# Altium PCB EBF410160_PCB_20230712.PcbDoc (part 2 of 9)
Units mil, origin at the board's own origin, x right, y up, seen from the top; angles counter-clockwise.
Board outline 5393.69 x 3858.26 mil, 6 copper layers (TOP, GND02, ART03, POW04, GND05, BOTTOM), stack 47.2 mil thick; 572 components, 434 nets, 2057 pads, 1177 vias.
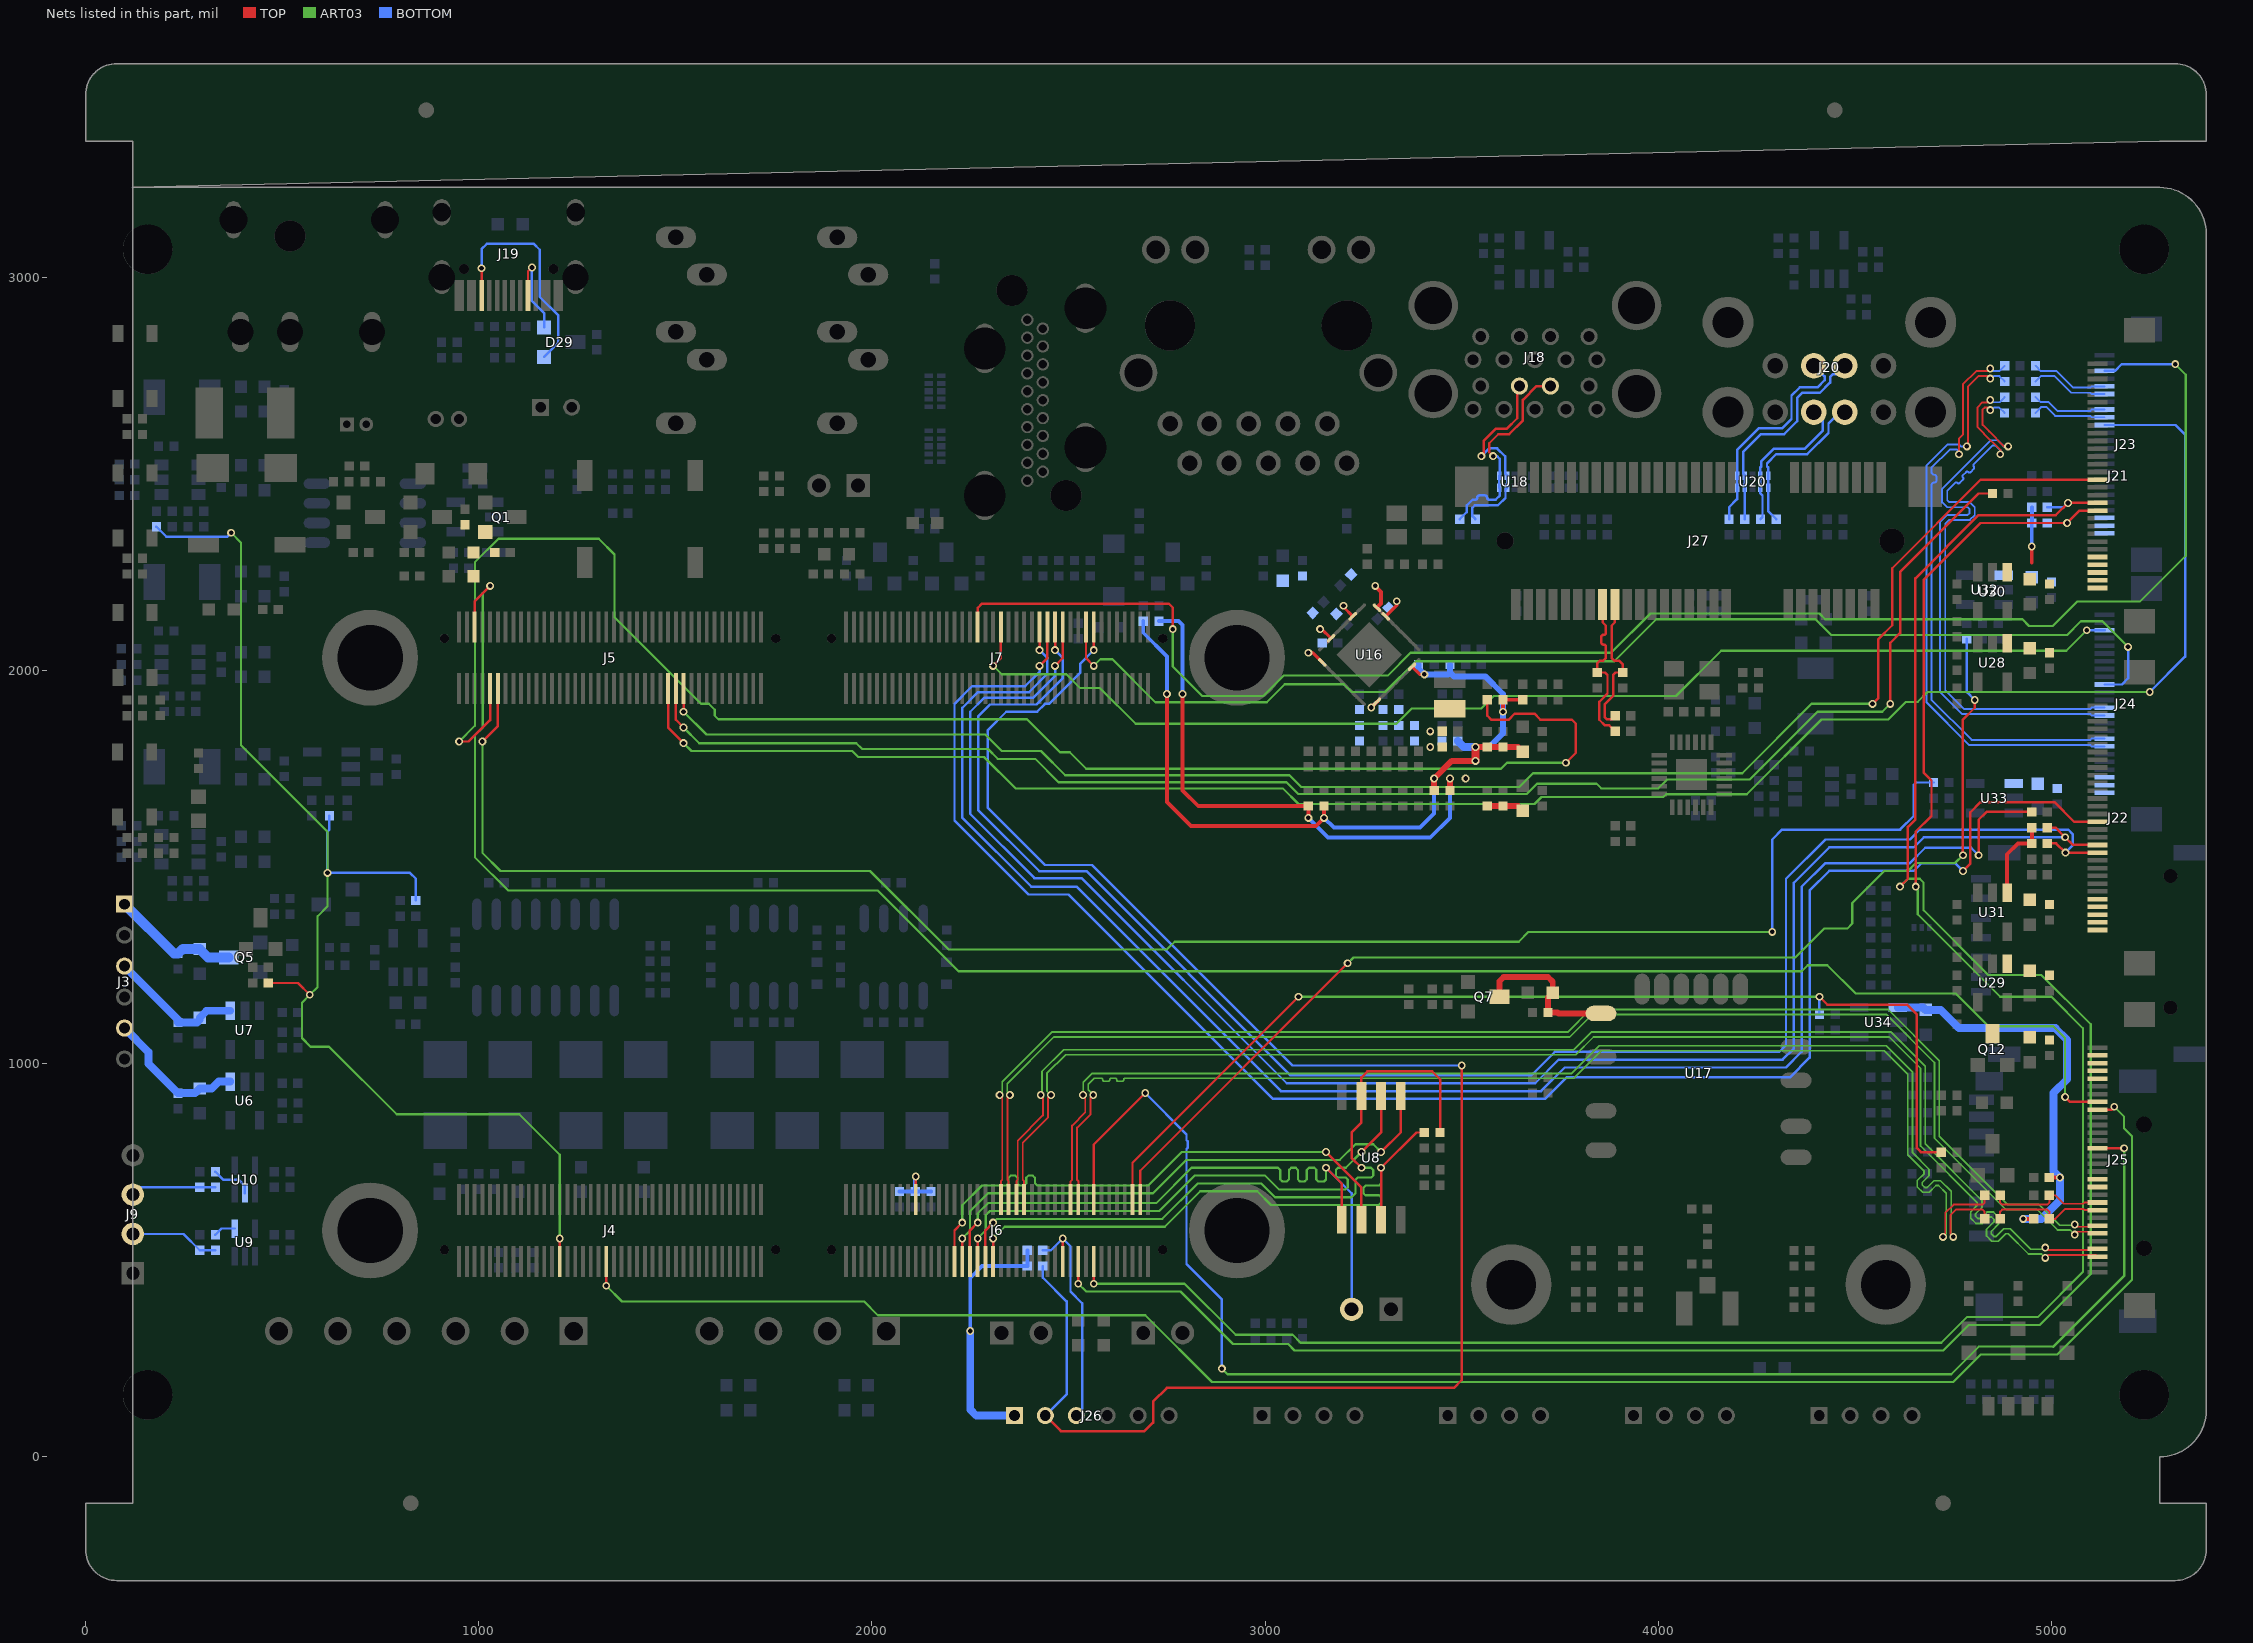
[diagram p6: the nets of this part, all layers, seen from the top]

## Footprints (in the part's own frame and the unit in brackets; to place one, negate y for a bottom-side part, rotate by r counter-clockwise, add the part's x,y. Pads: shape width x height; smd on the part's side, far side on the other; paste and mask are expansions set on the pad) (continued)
HDMI-SMD [mm] "HDMI-SMD"
  round 0.8 / inner round 1.524 / far side round 0.8 hole 0.55: 1(1.194,0.5) 3(0.039,0.5) 4(-0.531,-0.5) 6(-1.687,-0.5) 7(-2.271,0.5) 9(-3.425,0.5) 10(-3.998,-0.5) 12(-5.154,-0.5) 13(-5.736,0.5) 14(-6.31,-0.5) 15(-6.891,0.5) 16(-7.467,-0.5) 18(-8.623,-0.5) 19(-9.2,0.5)
  round 0.8 hole 0.55: 2(0.626,-0.5) 5(-1.116,0.5) 8(-2.843,-0.5) 11(-4.581,0.5) 17(-8.045,0.5)
  oval 3.2x1.4 / inner round 1.524 / far side oval 3.2x1.4 hole 2.7 slot 0.9 at 90 deg: G1(-10.156,3.25) G2(-0.656,3.25) G3(-7.056,-3.25) G4(1.945,-3.25)
  round 2 hole 2 unplated: ""(-10.156,-2) ""(3.094,1.5)
  silkscreen extent -11.51,-3.83 11.73,3.79, body extent -11.86,-4.05 11.86,4.05, height 3.81
HY911130A [mm] "HY911130A"
  round 1.6 / inner round 1.524 / far side round 1.6 hole 1: 1(5.72,-8.74) 2(4.45,-6.2) 3(3.18,-8.74) 4(1.91,-6.2) 5(0.64,-8.74) 6(-0.63,-6.2) 7(-1.9,-8.74) 8(-3.17,-6.2) 9(-4.44,-8.74) 10(-5.71,-6.2)
  round 1.8 / inner round 1.524 / far side round 1.8 hole 1.2: 11(6.625,5.05) 12(4.085,5.05) 13(-4.085,5.05) 14(-6.625,5.05)
  round 2.43 hole 1.83: 15(7.745,-2.9) 16(-7.745,-2.9)
  round 3.25 hole 3.25 unplated: ""(-5.715,0.15) ""(5.715,0.15)
  silkscreen extent -8.02,-10.25 8.02,11.05, body extent -9.2,-11.05 9.2,11.05, height 3.81
L0603 [mil] "L0603"
  rect 31.5x31.5 smd: 1(-31.5,0) 2(31.5,0)
  silkscreen extent -54,-24 55,24, body extent -47,-16 47,16, height 150
L2520 [mil] "L2520"
  rect 44x80 smd: 1(-37.75,0) 2(37.75,0)
  silkscreen extent -68,-48 68,48, body extent -65,-45 65,45, height 150
L4520 [mil] "L4520"
  rect 55.12x90.55 smd: 1(-70.97,-0.1) 2(70.77,-0.1)
  silkscreen extent -91,-87 90,87, body extent -91,-87 91,87, height 150
LED0603 [mil] "LED0603"
  rect 36.61x38.58 smd: 1(30.32,0) 2(-30.31,0)
  silkscreen extent -60,-31 80,31, body extent -49,-19 49,19, height 150
MARK#1 [mil] "MARK"
  round 40 smd far side: 1(-39.37,3543.3) 1(0,0) 1(3582.67,0) 1(3858.26,3543.3)
  body extent -79,-40 3898,3583, height 150
MARK#2 [mil] "MARK"
  round 40 smd far side: 1(-3622.04,3543.3) 1(-3582.67,0) 1(0,0) 1(275.59,3543.3)
  body extent -3662,-40 316,3583, height 150
MARK#3 [mil] "MARK"
  round 40 smd far side: 1(-3897.63,0) 1(-3858.26,-3543.3) 1(-275.59,-3543.3) 1(0,0)
  body extent -3938,-3583 40,40, height 150
MARK#4 [mil] "MARK"
  round 40 smd far side: 1(0,0) 1(39.37,-3543.3) 1(3622.04,-3543.3) 1(3897.63,0)
  body extent -40,-3583 3938,40, height 150
MARK#5 [mil] "MARK"
  round 40 smd: 1(-39.37,-3543.3) 1(0,0) 1(3582.67,0) 1(3858.26,-3543.3)
  body extent -79,-3583 3898,40, height 150
MARK#6 [mil] "MARK"
  round 40 smd: 1(-3622.04,-3543.3) 1(-3582.67,0) 1(0,0) 1(275.59,-3543.3)
  body extent -3662,-3583 316,40, height 150
MARK#7 [mil] "MARK"
  round 40 smd: 1(-3897.63,0) 1(-3858.26,3543.3) 1(-275.59,3543.3) 1(0,0)
  body extent -3938,-40 40,3583, height 150
MARK#8 [mil] "MARK"
  round 40 smd: 1(0,0) 1(39.37,3543.3) 1(3622.04,3543.3) 1(3897.63,0)
  body extent -40,-40 3938,3583, height 150
NANO_SIM [mm] "NANO_SIM"
  rect 0.5x1.3 smd: 1(0.25,6.94) 2(-2.29,6.94) 3(-4.83,6.94) 4(2.47,6.94) 5(1.52,6.94) 6(-1.02,6.94) 7(-3.56,6.94)
  rect 1x2.1 smd: 8(-6.5,5.46) 9(6.5,5.46) 10(-6.5,-6.54) 11(6.5,-6.54)
  round 0.9 hole 0.9 unplated: ""(-5,-5.29) ""(3.5,-5.29)
  silkscreen extent -6.14,-7.6 6.14,5.9, body extent -7.05,-7.64 7.05,7.64, height 3.81
NPTH_M3 [mm] "NPTH_M3"
  round 3.2 / inner round 1.524 / far side round 3.2 hole 3.2 unplated: 1(0,0)
  body extent -3.11,-3.11 3.11,3.11, height 3.81
PCIE_52P [mm] "PCIE_52P"
  rect 0.6x2 smd: 1(-11.8,-4.1) 2(-11.4,4.1) 3(-11,-4.1) 4(-10.6,4.1) 5(-10.2,-4.1) 6(-9.8,4.1) 7(-9.4,-4.1) 8(-9,4.1) 9(-8.6,-4.1) 10(-8.2,4.1) 11(-7.8,-4.1) 12(-7.4,4.1) 13(-7,-4.1) 14(-6.6,4.1) 15(-6.2,-4.1) 16(-5.8,4.1) 17(-2.2,-4.1) 18(-1.8,4.1) 19(-1.4,-4.1) 20(-1,4.1) 21(-0.6,-4.1) 22(-0.2,4.1) 23(0.2,-4.1) 24(0.6,4.1) 25(1,-4.1) 26(1.4,4.1) 27(1.8,-4.1) 28(2.2,4.1) 29(2.6,-4.1) 30(3,4.1) 31(3.4,-4.1) 32(3.8,4.1) 33(4.2,-4.1) 34(4.6,4.1) 35(5,-4.1) 36(5.4,4.1) 37(5.8,-4.1) 38(6.2,4.1) 39(6.6,-4.1) 40(7,4.1) 41(7.4,-4.1) 42(7.8,4.1) 43(8.2,-4.1) 44(8.6,4.1) 45(9,-4.1) 46(9.4,4.1) 47(9.8,-4.1) 48(10.2,4.1) 49(10.6,-4.1) 50(11,4.1) 51(11.4,-4.1) 52(11.8,4.1)
  rect 2.15x2.6 smd: 53(14.65,-3.5) 54(-14.65,-3.5)
  round 1.6 hole 1.6 unplated: ""(-12.5,0)
  round 1.1 hole 1.1 unplated: ""(12.5,0)
  silkscreen extent -15,-4.6 15,49.64, body extent -15.8,-5.2 15.8,5.2, height 3.81
PH-1X2-2P0_L [mm] "PH-1X2-2P0_L"
  rect 1.1x1.1 / inner round 1.524 / far side rect 1.1x1.1 hole 0.7: 1(-1,-0.6)
  round 1.1 / inner round 1.524 / far side round 1.1 hole 0.7: 2(1,-0.6)
  silkscreen extent -3,-2.6 3,2.6, body extent -3.1,-2.7 3.1,2.7, height 3.81
PH-1X4-2P0 [mm] "PH-1X4-2P0"
  rect 1.1x1.1 / inner round 1.524 / far side rect 1.1x1.1 hole 0.7: 1(-3,-0.6)
  round 1.1 / inner round 1.524 / far side round 1.1 hole 0.7: 2(-1,-0.6) 3(1,-0.6)
  round 1.1 hole 0.7: 4(3,-0.6)
  silkscreen extent -5,-2.6 5,2.6, body extent -5.1,-2.7 5.1,2.7, height 3.81
PH-1X6-2P0#1 [mm] "PH-1X6-2P0"
  rect 1.1x1.1 / inner round 1.524 / far side rect 1.1x1.1 hole 0.7: 1(-5,-0.6)
  round 1.1 hole 0.7: 2(-3,-0.6) 4(1,-0.6) 6(5,-0.6)
  round 1.1 / inner round 1.524 / far side round 1.1 hole 0.7: 3(-1,-0.6) 5(3,-0.6)
  silkscreen extent -7,-2.6 7,2.6, body extent -7.1,-2.7 7.1,2.7, height 3.81
PH-1X6-2P0#2 [mm] "PH-1X6-2P0"
  rect 1.1x1.1 / inner round 1.524 / far side rect 1.1x1.1 hole 0.7: 1(-5,-0.6)
  round 1.1 / inner round 1.524 / far side round 1.1 hole 0.7: 2(-3,-0.6) 3(-1,-0.6) 4(1,-0.6) 5(3,-0.6)
  round 1.1 hole 0.7: 6(5,-0.6)
  silkscreen extent -7,-2.6 7,2.6, body extent -7.1,-2.7 7.1,2.7, height 3.81
QFN24 [mm] "QFN24"
  rect 1x0.3 smd: 1(-2.1,1.25) 2(-2.1,0.75) 3(-2.1,0.25) 4(-2.1,-0.25) 5(-2.1,-0.75) 6(-2.1,-1.25) 13(2.1,-1.25) 14(2.1,-0.75) 15(2.1,-0.25) 16(2.1,0.25) 17(2.1,0.75) 18(2.1,1.25)
  rect 0.3x1 smd: 7(-1.25,-2.1) 8(-0.75,-2.1) 9(-0.25,-2.1) 10(0.25,-2.1) 11(0.75,-2.1) 12(1.25,-2.1) 19(1.25,2.1) 20(0.75,2.1) 21(0.25,2.1) 22(-0.25,2.1) 23(-0.75,2.1) 24(-1.25,2.1)
  rect 2x2 smd: 25(0,0)
  silkscreen extent -3.35,-2.1 2.1,2.1, body extent -2.7,-2.7 2.7,2.7, height 3.81
QFP_40P_R [mil] "QFP_40P_R"
  oval 8.66x27.17 smd: 1(-98.43,70.87) 2(-98.43,55.12) 3(-98.43,39.37) 4(-98.43,23.62) 5(-98.43,7.87) 6(-98.43,-7.87) 7(-98.43,-23.62) 8(-98.43,-39.37) 9(-98.43,-55.12) 10(-98.43,-70.87) 21(98.43,-70.87) 22(98.43,-55.12) 23(98.43,-39.37) 24(98.43,-23.62) 25(98.43,-7.87) 26(98.43,7.87) 27(98.43,23.62) 28(98.43,39.37) 29(98.43,55.12) 30(98.43,70.87)
  oval 27.17x8.66 smd: 11(-70.87,-98.43) 12(-55.12,-98.43) 13(-39.37,-98.43) 14(-23.62,-98.43) 15(-7.87,-98.43) 16(7.87,-98.43) 17(23.62,-98.43) 18(39.37,-98.43) 19(55.12,-98.43) 20(70.87,-98.43) 31(70.87,98.43) 32(55.12,98.43) 33(39.37,98.43) 34(23.62,98.43) 35(7.87,98.43) 36(-7.87,98.43) 37(-23.62,98.43) 38(-39.37,98.43) 39(-55.12,98.43) 40(-70.87,98.43)
  rect 118.11x118.11 smd: 41(0,0)
  silkscreen extent -144,-98 98,98, body extent -116,-116 116,116, height 150
R0402#1 [mil] "R0402"
  rect 23.6x23.6 smd: 1(19.68,0) 2(-19.68,0)
  silkscreen extent -37,-17 37,17, body extent -37,-17 37,17, height 150
R0402#2 [mil] "R0402"
  rect 23.6x23.6 smd: 1(-19.68,0) 2(19.68,0)
  silkscreen extent -37,-17 37,17, body extent -37,-17 37,17, height 150
R0603 [mil] "R0603"
  rect 31.5x31.5 smd: 1(-31.5,0) 2(31.5,0)
  silkscreen extent -54,-24 55,24
RL-UM02WBS-8723BU [mm] "RL-UM02WBS-8723BU"
  oval 2x1 smd: 1(-6.3,4.122) 2(-6.3,2.122) 3(-6.3,-0.858) 4(-6.3,-3.018) 5(6.3,3.652) 6(6.3,1.122) 7(6.3,-2.378) 8(6.3,-5.178)
  oval 1x2 smd: 9(3.65,-6.748) 10(2.38,-6.748) 11(1.11,-6.748) 12(-0.16,-6.748) 13(-1.43,-6.748) 14(-2.7,-6.748)
  silkscreen extent -6.1,-6.55 6.1,6.45, body extent -6.1,-6.45 6.1,6.45, height 3.81
SGDBF-05-80P-H30 [mm] "SGDBF-05-80P-H30"
  rect 0.25x2 smd: 1(9.75,-2) 2(9.75,2) 3(9.25,-2) 4(9.25,2) 5(8.75,-2) 6(8.75,2) 7(8.25,-2) 8(8.25,2) 9(7.75,-2) 10(7.75,2) 11(7.25,-2) 12(7.25,2) 13(6.75,-2) 14(6.75,2) 15(6.25,-2) 16(6.25,2) 17(5.75,-2) 18(5.75,2) 19(5.25,-2) 20(5.25,2) 21(4.75,-2) 22(4.75,2) 23(4.25,-2) 24(4.25,2) 25(3.75,-2) 26(3.75,2) 27(3.25,-2) 28(3.25,2) 29(2.75,-2) 30(2.75,2) 31(2.25,-2) 32(2.25,2) 33(1.75,-2) 34(1.75,2) 35(1.25,-2) 36(1.25,2) 37(0.75,-2) 38(0.75,2) 39(0.25,-2) 40(0.25,2) 41(-0.25,-2) 42(-0.25,2) 43(-0.75,-2) 44(-0.75,2) 45(-1.25,-2) 46(-1.25,2) 47(-1.75,-2) 48(-1.75,2) 49(-2.25,-2) 50(-2.25,2) 51(-2.75,-2) 52(-2.75,2) 53(-3.25,-2) 54(-3.25,2) 55(-3.75,-2) 56(-3.75,2) 57(-4.25,-2) 58(-4.25,2) 59(-4.75,-2) 60(-4.75,2) 61(-5.25,-2) 62(-5.25,2) 63(-5.75,-2) 64(-5.75,2) 65(-6.25,-2) 66(-6.25,2) 67(-6.75,-2) 68(-6.75,2) 69(-7.25,-2) 70(-7.25,2) 71(-7.75,-2) 72(-7.75,2) 73(-8.25,-2) 74(-8.25,2) 75(-8.75,-2) 76(-8.75,2) 77(-9.25,-2) 78(-9.25,2) 79(-9.75,-2) 80(-9.75,2)
  round 0.6 hole 0.6 unplated: ""(-10.7,-1.25) ""(10.7,-1.25)
  silkscreen extent -11.4,-3.75 11.4,2, body extent -11.5,-3.1 11.5,3.1, height 3.81
SGDBM-05-80P-H10 [mm] "SGDBM-05-80P-H10"
  rect 0.25x2 smd: 1(-9.75,-2) 2(-9.75,2) 3(-9.25,-2) 4(-9.25,2) 5(-8.75,-2) 6(-8.75,2) 7(-8.25,-2) 8(-8.25,2) 9(-7.75,-2) 10(-7.75,2) 11(-7.25,-2) 12(-7.25,2) 13(-6.75,-2) 14(-6.75,2) 15(-6.25,-2) 16(-6.25,2) 17(-5.75,-2) 18(-5.75,2) 19(-5.25,-2) 20(-5.25,2) 21(-4.75,-2) 22(-4.75,2) 23(-4.25,-2) 24(-4.25,2) 25(-3.75,-2) 26(-3.75,2) 27(-3.25,-2) 28(-3.25,2) 29(-2.75,-2) 30(-2.75,2) 31(-2.25,-2) 32(-2.25,2) 33(-1.75,-2) 34(-1.75,2) 35(-1.25,-2) 36(-1.25,2) 37(-0.75,-2) 38(-0.75,2) 39(-0.25,-2) 40(-0.25,2) 41(0.25,-2) 42(0.25,2) 43(0.75,-2) 44(0.75,2) 45(1.25,-2) 46(1.25,2) 47(1.75,-2) 48(1.75,2) 49(2.25,-2) 50(2.25,2) 51(2.75,-2) 52(2.75,2) 53(3.25,-2) 54(3.25,2) 55(3.75,-2) 56(3.75,2) 57(4.25,-2) 58(4.25,2) 59(4.75,-2) 60(4.75,2) 61(5.25,-2) 62(5.25,2) 63(5.75,-2) 64(5.75,2) 65(6.25,-2) 66(6.25,2) 67(6.75,-2) 68(6.75,2) 69(7.25,-2) 70(7.25,2) 71(7.75,-2) 72(7.75,2) 73(8.25,-2) 74(8.25,2) 75(8.75,-2) 76(8.75,2) 77(9.25,-2) 78(9.25,2) 79(9.75,-2) 80(9.75,2)
  round 0.6 hole 0.6 unplated: ""(-10.7,-1.25) ""(10.7,-1.25)
  silkscreen extent -11.4,-3.75 11.4,2, body extent -11.5,-3.1 11.5,3.1, height 3.81
SMA214-CA [mm] "SMA214-CA"
  rect 2.1x1.8 smd: 1(-2.2,0) 2(2.2,0)
  silkscreen extent -2.2,-1.3 2.2,1.3, body extent -3.3,-1.4 3.3,1.4, height 3.81
SMB-CA [mm] "SMB-CA"
  rect 2.4x2.8 smd: 1(-2.3,0) 2(2.3,0)
  silkscreen extent -2.3,-1.8 2.3,1.8, body extent -3.5,-1.8 3.5,1.8, height 3.81
SMD4-6R80X2R50 [mm] "SMD4-6R80X2R50"
  rect 0.8x1.2 smd: 1(1.905,-0.7) 2(0.635,-0.7) 3(-0.635,-0.7) 4(-1.905,-0.7)
  silkscreen extent -3.4,-2.26 3.4,1.3, body extent -3.6,-1.5 3.6,1.5, height 3.81
SMTSO-M2R5 [mm] "SMTSO-M2R5"
  round 6.2 / inner round 5.2 / far side round 5.2 hole 4.22: 1(0,0)
  body extent -3.21,-3.21 3.21,3.21, height 3.81
SOD523 [mm] "SOD523"
  rect 0.6x0.7 smd: 1(-0.71,0) 2(0.71,0)
  silkscreen extent -1.3,-0.5 0.6,0.5, body extent -1.1,-0.4 1.1,0.4, height 3.81
SOD-123 [mm] "SOD-123"
  rect 1.2x1.4 smd: 1(1.7,0) 2(-1.7,0)
  silkscreen extent -1.8,-0.9 1.8,0.9, body extent -2.4,-1 2.4,1, height 3.81
SOIC8-208 [mil] "SOIC8-208"
  rect 70x25 smd: 1(-157.48,75) 2(-157.48,25) 3(-157.48,-25) 4(-157.48,-75) 5(157.48,-75) 6(157.48,-25) 7(157.48,25) 8(157.48,75)
  silkscreen extent -235,-104 100,104, body extent -197,-110 197,110, height 150
SOIC16 [mil] "SOIC16"
  oval 80x24 smd: 1(-109.8,174.8) 2(-109.8,125.2) 3(-109.8,74.8) 4(-109.8,25.2) 5(-109.8,-25.2) 6(-109.8,-74.8) 7(-109.8,-125.2) 8(-109.8,-174.8) 9(109.8,-174.8) 10(109.8,-125.2) 11(109.8,-74.8) 12(109.8,-25.2) 13(109.8,25.2) 14(109.8,74.8) 15(109.8,125.2) 16(109.8,174.8)
  silkscreen extent -179,-197 59,197, body extent -157,-205 157,205, height 150
SOP8 [mm] "SOP8"
  oval 0.6x1.8 smd: 1(-1.905,-2.5) 2(-0.635,-2.5) 3(0.635,-2.5) 4(1.905,-2.5) 5(1.905,2.5) 6(0.635,2.5) 7(-0.635,2.5) 8(-1.905,2.5)
  silkscreen extent -2.5,-4.15 2.5,1.4, body extent -2.5,-3.5 2.5,3.5, height 3.81
SOP-8 [mm] "SOP-8"
  oval 0.7x1.7 smd: 1(-1.903,-3.104) 2(-0.633,-3.104) 3(0.637,-3.104) 4(1.907,-3.104) 5(1.907,3.096) 6(0.637,3.096) 7(-0.633,3.096) 8(-1.903,3.096)
  silkscreen extent -3.5,-3.09 3.5,2, body extent -3.5,-3.99 3.5,3.99, height 3.81
SOT23#1 [mil] "SOT23"
  rect 36x36 smd: 1(-37.5,-43.5) 2(37.5,-43.5)
  rect 36x50 smd: 3(0,36.5)
  silkscreen extent -55,-54 55,36, body extent -56,-62 56,62, height 150
SOT23#2 [mil] "SOT23"
  rect 36x36 smd: 1(37.5,43.5) 2(-37.5,43.5)
  rect 36x50 smd: 3(0,-36.5)
  silkscreen extent -55,-36 55,54, body extent -56,-62 56,62, height 150
SOT23-5#1 [mm] "SOT23-5"
  rect 0.599x1.199 smd: 1(0.95,1.25) 2(0,1.25) 3(-0.95,1.25) 4(-0.95,-1.25) 5(0.95,-1.25)
  silkscreen extent -1.5,-0.9 1.91,1.91, body extent -1.6,-1.9 1.6,1.9, height 3.81
SOT23-5#2 [mm] "SOT23-5"
  rect 0.599x1.199 smd: 1(-0.95,-1.25) 2(0,-1.25) 3(0.95,-1.25) 4(0.95,1.25) 5(-0.95,1.25)
  silkscreen extent -2.16,-1.78 1.5,0.9, body extent -1.6,-1.9 1.6,1.9, height 3.81
SOT23_6 [mm] "SOT23_6"
  rect 0.7x0.9 smd: 1(-0.95,-1.2) 2(0,-1.2) 3(0.95,-1.2) 4(0.95,1.2) 5(0,1.2) 6(-0.95,1.2)
  silkscreen extent -1.78,-2.29 1.4,0.6, body extent -1.4,-1.2 1.4,1.2, height 3.81
SOT563 [mm] "SOT563"
  rect 0.3x0.45 smd: 1(0.499,0.65) 2(-0.001,0.65) 3(-0.501,0.65) 4(-0.501,-0.7) 5(-0.001,-0.7) 6(0.499,-0.7)
  silkscreen extent -0.85,-0.84 0.85,1.68, body extent -0.8,-0.98 0.8,0.98, height 3.81
SOT-353 [mil] "SOT-353"
  rect 16x47 smd: 1(25.91,35.43) 2(0.31,35.43) 3(-25.28,35.43) 4(-25.28,-35.43) 5(25.91,-35.43)
  silkscreen extent -45,-70 55,80, body extent -40,-65 40,65, height 150
SW_3_2X4_2 [mil] "SW_3_2X4_2"
  rect 43.31x27.56 smd: 1(-82.97,43) 2(82.39,43) 3(-82.97,-43.62) 4(82.39,-43.62)
  silkscreen extent -83,-63 82,63, body extent -83,-63 83,63, height 150
T3R2-5R2_TOPSMT [mil] "T3R2-5R2_TOPSMT"
  round 204.72 hole 125.98: 1(0,0)
TFCARD [mil] "TFCARD"
  rect 27.56x62.99 smd: 1(88.58,206.82) 2(45.27,206.82) 3(1.97,206.82) 4(-41.34,206.82) 5(-84.65,206.82) 6(-127.95,206.82) 7(-171.26,206.82) 8(-214.57,206.82) 9(-257.88,206.82)
  rect 47.24x70 smd: 10(-305.12,187.13)
  rect 60x95 smd: 11(-305.12,-190.82) 12(305.12,-190.82)
  rect 70x70 smd: 13(269.68,187.13)
  round 40 hole 40 unplated: ""(-194.88,-206.57) ""(120.08,-206.57)
  silkscreen extent -289,-365 281,179, body extent -335,-238 335,238, height 150
TYPE-C-31-M-12 [mm] "TYPE-C-31-M-12"
  rect 0.3x2 smd: A1(-3.35,3.539) A4(-2.55,3.539) A5(-1.25,3.539) A6(-0.249,3.539) A7(0.249,3.539) A8(1.25,3.539) A9(2.55,3.539) A12(3.35,3.539) B1(3.05,3.539) B4(2.25,3.539) B5(1.75,3.539) B6(0.749,3.539) B7(-0.749,3.539) B8(-1.75,3.539) B9(-2.25,3.539) B12(-3.05,3.539)
  oval 1.1x1.7 / inner round 1.524 / far side oval 1.1x1.7 hole 1.2 slot 0.6 at 0 deg: C1(-4.32,-1.84) C2(4.32,-1.84)
  oval 1.1x2.2 / inner round 1.524 / far side oval 1.1x2.2 hole 1.7 slot 0.6 at 0 deg: C3(-4.32,2.351) C4(4.32,2.351)
  round 0.65 hole 0.65 unplated: ""(-2.89,1.82) ""(2.89,1.82)
  silkscreen extent -4.5,-4.43 4.5,2.86, body extent -4.87,-4.54 4.87,4.54, height 3.81
UFL-3 [mil] "UFL-3"
  rect 41.34x41.34 smd: 1(0,-40.86)
  rect 41.34x86.61 smd: 2(-59.06,18.2) 3(59.06,18.2)
  body extent -80,-62 80,62, height 150
USB3D0-AF-18P [mm] "USB3D0-AF-18P"
  round 1.1 / inner round 1.524 / far side round 1.1 hole 0.7: 1(-3.5,2.9) 2(-1,2.9) 3(1,2.9) 5(4,4.4) 6(2,4.4) 8(-2,4.4) 9(-4,4.4) 10(-3.5,6.1) 11(-1,6.1) 12(1,6.1) 14(4,7.6) 15(2,7.6) 17(-2,7.6) 18(-4,7.6)
  round 1.1 hole 0.7: 4(3.5,2.9) 7(0,4.4) 13(3.5,6.1) 16(0,7.6)
  round 3.2 hole 2.4: 19(6.57,0.9) 20(6.57,6.58) 21(-6.57,6.58) 22(-6.57,0.9)
  silkscreen extent -7.26,-8.74 7.19,8.77, body extent -8.4,-8.8 8.4,8.8, height 3.81
USB-A-D [mil] "USB-A-D"
  round 65 / inner round 60 / far side round 65 hole 39.37: 1(137.8,-114.18) 2(39.37,-114.18) 3(-39.37,-114.18) 7(137.8,3.93) 8(39.37,3.93) 9(-39.37,3.93)
  round 65 hole 39.37: 4(-137.8,-114.18) 10(-137.8,3.93)
  round 129.92 hole 78.74: 5(-257.87,-114.18) 6(257.87,-114.18) 11(-257.87,114.17) 12(257.87,114.17)
  silkscreen extent -258,-154 258,535
USON_10#1 [mm] "USON_10"
  rect 0.3x0.55 smd: 1(1,0.4) 2(0.5,0.4) 4(-0.5,0.4) 5(-1,0.4) 6(-1,-0.4) 7(-0.5,-0.4) 9(0.5,-0.4) 10(1,-0.4)
  rect 0.4x0.55 smd: 3(0,0.4) 8(0,-0.4)
  silkscreen extent -1.3,-0.5 1.95,0.95, body extent -1.3,-0.7 1.3,0.7, height 3.81
USON_10#2 [mm] "USON_10"
  rect 0.3x0.55 smd: 1(-1,-0.4) 2(-0.5,-0.4) 4(0.5,-0.4) 5(1,-0.4) 6(1,0.4) 7(0.5,0.4) 9(-0.5,0.4) 10(-1,0.4)
  rect 0.4x0.55 smd: 3(0,-0.4) 8(0,0.4)
  silkscreen extent -1.95,-0.95 1.3,0.5
XH2P54-4P [mm] "XH2P54-4P"
  rect 1.45x1.45 / inner round 1.524 / far side rect 1.45x1.45 hole 0.85: 1(-3.81,0.508)
  round 1.45 / inner round 1.524 / far side round 1.45 hole 0.85: 2(-1.27,0.508) 3(1.27,0.508)
  round 1.45 hole 0.85: 4(3.81,0.508)
  silkscreen extent -6.51,-3.03 6.51,3.05, body extent -6.48,-3.05 6.48,3.05, height 3.81
ZH1P5MM_TH_2P [mm] "ZH1P5MM_TH_2P"
  round 1.05 / inner round 1.524 / far side round 1.05 hole 0.65: 1(-0.75,0.65)
  round 1.05 hole 0.65: 2(0.75,0.65)
  silkscreen extent -2.25,-1.85 2.25,1.85, body extent -2.2,-1.85 2.2,1.85, height 3.81

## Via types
v1: diameter 20, hole 12, TOP to BOTTOM, 1177 vias

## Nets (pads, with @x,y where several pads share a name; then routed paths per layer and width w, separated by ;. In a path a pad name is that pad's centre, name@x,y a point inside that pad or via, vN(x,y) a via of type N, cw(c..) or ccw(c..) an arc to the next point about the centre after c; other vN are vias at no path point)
1V05_AVDD_PHY: C97.1 C98.1 C99.1 C100.1 R124.2 U16.3 U16.8 U16.38 | length 124.1
  TOP w8: v1(3140,2105) 3144.32,2105 U16.8@3167.56,2081.76 ; v1(3199.46,2164.46) 3199.46,2161.22 U16.3@3223.24,2137.44 ; U16.38@3306.76,2137.44 3334.91,2165.58 v1(3334.91,2175.83)
1V05_DVDD_PHY: C93.1 C94.1 C95.1 C96.1 R123.1 U16.21 | length 20.5
  TOP w10: v1(3270,1905.8) U16.21@3284.49,1920.29
1V05_PHY: C79.1 C80.1 L4.2 R123.2 R124.1
  other v1: 3420,1805 3420,1845
1V8_DVDD_PHY: C101.1 C102.1 L7.1 R89.2 R90.1 R106.1 R119.1 | length 1479.1
  TOP w10: v1(2790,1940) 2790,1695 2830,1655 3109.68,1655 R106.1@3110,1655.32 v1(3110,1625)
  TOP w15: R90.1@3470,1694.68 v1(3470,1725) ; C102.1@3565,1655.32 C101.1@3605,1655.32 3643.18,1655.32 L7.1@3655,1643.5
  BOTTOM w10: R119.1@2730,2125.32 2735,2125.32 2735.68,2126 2780,2126 2790,2116 v1(2790,1940) ; v1(3110,1625) 3160,1575 3420,1575 3470,1625 v1(3470,1725)
  other v1: 3510,1725
3V3_AVDD_PHY: C89.1 C90.1 C91.1 L6.1 U16.11 U16.40 | length 111.3
  TOP w8: v1(3110,2045) 3120.8,2045 U16.11@3145.29,2020.51
  TOP w10: v1(3280,2215) 3295,2200 3295,2170.22 U16.40@3284.49,2159.71
3V3_DVDD_PHY: C85.1 C86.1 C87.1 L5.1 R91.2 R92.2 R107.2 R110.1 R118.2 R120.1 R122.2 U16.29 | length 2290
  TOP w8: U16.29@3373.57,2009.37 3392.95,1990 v1(3405,1990)
  TOP w10: v1(2750,1940) 2750,1665 2811,1604 3129,1604 v1(3150,1625) R107.2@3150,1655.32 ; v1(3605,1895) R110.1@3605,1925.32 R118.2@3655,1925.32
  TOP w15: R91.2@3430,1694.68 v1(3430,1725) 3475,1770 v1(3535,1770) ; v1(3535,1805) 3535.32,1805.32 C86.1@3565,1805.32 C85.1@3605,1805.32 3643.18,1805.32 L5.1@3655,1793.5
  TOP w20: v1(3535,1770) v1(3535,1805)
  BOTTOM w10: R120.1@2690,2125.32 2690,2095.73 2750,2035.73 v1(2750,1940) ; v1(3150,1625) 3175,1600 3394,1600 3430,1636 v1(3430,1725)
  BOTTOM w15: C87.1@3390,2015.32 3390,2005 v1(3405,1990) 3465,1990 3470,1995 ; R122.2@3470,2015.32 3470,1995 ; v1(3535,1805) 3570,1805 3605,1840 v1(3605,1895) 3605,1940 3560,1985 3480,1985 3470,1995
  BOTTOM w20: R92.2@3490,1820.32 3505.32,1805 v1(3535,1805)
3V3_EDP: C149.1 C150.1 J25.12 J25.13 J26.1 R188.1 R189.1 R190.1 U34.1 | length 1711.9
  TOP w10: v1(4928.52,605) R188.1@4955.32,605 ; C150.1@4994.68,710 v1(5021.48,710)
  BOTTOM w10: v1(2250,320) 2250,455 2280,485 R189.1@2395.32,485 R190.1@2395.32,525
  BOTTOM w20: v1(2250,320) 2250,120 2265.51,104.49 J26.1@2362.2,104.49 ; U34.1@4609.21,1142.4 4674.1,1142.4 C149.1@4680,1136.5 4718.5,1136.5 4765,1090 5010,1090 5040,1060 5040,960 5005,925 5005,726.48 v1(5021.48,710) 5021.48,651.48 4975,605 v1(4928.52,605)
3V3_IMAGE_1: C136.1 C137.1 J21.4 J21.5 R162.1 R166.1 U30.1 | length 140.1
  TOP w10: 4950,2275 v1(4950,2315)
  BOTTOM w10: v1(4950,2315) 4950,2374.68 R162.1@4950.32,2375 R166.1@4950.32,2415
3V3_IMAGE_2: C138.1 C139.1 J22.4 J22.5 R164.1 R168.1 U31.1 | length 212.5
  TOP w10: U31.1@4887.4,1434.21 4887.4,1532.4 4915,1560 R164.1@4950.32,1560 R168.1@4950.32,1600
3V3_OUT: C42.1 C43.1 J3.5 U6.1 | length 366.9
  BOTTOM w20: J3.5@98.74,1090.32 160,1029.06 160,999.68 C43.1@235,924.68 278.18,924.68 C42.1@290,936.5 320.75,936.5 338.46,954.21 U6.1@367.6,954.21
3V3_WLAN: C108.1 C109.1 Q7.3 U17.8 | length 403.1
  TOP w15: Q7.3@3596,1170 3596,1209.39 3606.61,1220 3719.75,1220 3731.5,1208.25 C108.1@3731.5,1180 3719.68,1168.18 C109.1@3719.68,1130 3743.98,1130 3746.51,1127.47 U17.8@3854.39,1127.47
5V0_CAM_1: C141.1 C142.1 J23.1 J23.2 J23.3 U32.1
5V0_CAM_2: C144.1 C145.1 J24.1 J24.2 J24.3 U33.1
5V0_IMAGE_1: C134.1 C135.1 J21.1 J21.2 J21.3 U28.1
5V0_IMAGE_2: C131.1 C132.1 J22.1 J22.2 J22.3 U29.1
5V_OUT: C45.1 C46.1 J3.3 U7.1 | length 347.3
  BOTTOM w20: J3.3@98.74,1247.8 235,1111.54 C46.1@235,1104.68 283.18,1104.68 290,1111.5 C45.1@290,1116.5 307.71,1134.21 U7.1@367.6,1134.21
12V_EDP: C152.1 C153.1 J25.26 J25.27 J25.28 J25.29 Q12.3
12V_OUT: C39.1 C40.1 J3.1 Q5.3 | length 331.1
  BOTTOM w25: J3.1@98.74,1405.28 224.34,1279.68 C40.1@235,1279.68 246.82,1291.5 C39.1@290,1291.5 311.5,1270 Q5.3@364,1270
B_DM1: J18.11 R129.1 U18.5 U18.6 | length 546.8
  TOP w6.23: v1(3580,2545) 3570,2555 3570,2577.88 3592.89,2600.77 3620.77,2600.77 3655.51,2635.51 3655.51,2688.26 3690.44,2723.19 J18.11@3725.66,2723.19
  BOTTOM w6.23: R129.1@3495,2384.68 3512.89,2402.57 3512.89,2419.66 3527.45,2434.23 3534.19,2434.23 ccw(c3534.19,2439.61) 3539.58,2439.61 cw(c3544.96,2439.61) 3544.96,2445 3559.11,2445 cw(c3559.11,2439.61) 3564.5,2439.61 ccw(c3569.88,2439.61) 3569.88,2434.23 3586.45,2434.23 3597.15,2444.93 3597.15,2462.74 U18.5@3595.63,2464.25 U18.6@3595.63,2495.75 3596.42,2496.54 3596.42,2538.45 3589.87,2545 v1(3580,2545)
B_DM2: J20.8 R138.1 U20.4 U20.7 | length 565.9
  BOTTOM w6.23: R138.1@4220,2384.68 4220,2463.94 U20.4@4220.31,2464.25 U20.7@4220.31,2495.75 4215.65,2500.41 4215.65,2555.65 4261.2,2601.2 4320.44,2601.2 4353.15,2633.9 4353.15,2693.14 4365.77,2705.77 4410.77,2705.77 4437.22,2732.22 4437.22,2746.66 4443.44,2752.89 4452.22,2752.89 J20.8@4474.47,2775.15
B_DM3: J20.2 R131.1 U20.1 U20.10 | length 417.4
  BOTTOM w6.23: R131.1@4300,2384.68 4279.37,2405.31 U20.1@4279.37,2464.25 U20.10@4279.37,2495.75 4279.37,2516.37 4276.64,2519.09 4276.64,2526.52 4300.12,2550 4378.95,2550 4433.05,2604.11 4433.05,2628.05 4462.04,2657.04 J20.2@4474.47,2657.04
B_DP1: J18.12 R130.1 U18.4 U18.7 | length 547.9
  TOP w6.23: v1(3550,2545) 3555.77,2550.77 3555.77,2583.77 3587,2615 3614.87,2615 3641.28,2641.41 3641.28,2717.55 J18.12@3646.92,2723.19
  BOTTOM w6.23: R130.1@3535,2384.68 3527.11,2392.57 3527.11,2413.77 3533.34,2420 3592.35,2420 3611.38,2439.03 3611.38,2460.32 U18.4@3615.31,2464.25 U18.7@3615.31,2495.75 3610.65,2500.41 3610.65,2544.35 3590.3,2564.7 3569.7,2564.7 v1(3550,2545)
B_DP2: J20.9 R139.1 U20.5 U20.6 | length 563.5
  BOTTOM w6.23: R139.1@4180,2384.68 4180,2415 4200.63,2435.63 U20.5@4200.63,2464.25 U20.6@4200.63,2495.75 4200.63,2505.69 4201.42,2506.48 4201.42,2561.55 4255.3,2615.43 4314.54,2615.43 4338.91,2639.8 4338.91,2699.04 4359.88,2720 4404.88,2720 4422.98,2738.11 4422.98,2747.89 J20.9@4395.73,2775.15
B_DP3: J20.3 R132.1 U20.2 U20.9 | length 398.4
  BOTTOM w6.23: R132.1@4260,2384.68 4265.14,2389.82 4265.14,2444.86 4259.69,2450.31 U20.2@4259.69,2464.25 U20.9@4259.69,2495.75 4259.69,2516.37 4262.41,2519.09 4262.41,2532.41 4294.23,2564.23 4373.05,2564.23 4418.82,2610 4418.82,2633.95 J20.3@4395.73,2657.04
BD_CH3: C53.1 J6.20 R34.2 R35.1 | length 177.2
  TOP w6.16: J6.20@2111.42,654.29 v1(2111.42,712.79)
  BOTTOM w10: R34.2@2070,674.68 C53.1@2110,674.68 ; v1(2111.42,712.79) 2110,711.37 C53.1@2110,674.68 ; R35.1@2150,674.68 C53.1@2110,674.68
CAM0_NRST: J7.35 J23.22 | length 4169.8
  TOP w6.16: J7.35@2268.9,2110.98 2268.9,2158.9 2280,2170 2755,2170 2765,2160 v1(2765,2105)
  ART03 w5.61: v1(2765,2105) 2765,2010 2840,1935 2995,1935 3046.8,1986.81 3311.8,1986.81 3370,2045 3880,2045 3980,2145 4410,2145 4425,2130 4926.23,2130 4943.04,2113.2 5003.19,2113.2 5065,2175 5225,2175 5341.81,2291.8 5341.81,2752.28 v1(5315,2779.08)
  BOTTOM w6.16: J23.22@5135.46,2762.01 5162.01,2762.01 5179.08,2779.08 v1(5315,2779.08)
CAM0_PWDN: J5.56 J23.15 | length 4973
  TOP w6.16: J5.56@1481.49,1953.5 1481.49,1854.37 v1(1520.86,1815)
  ART03 w5.61: v1(1520.86,1815) 1540.86,1795 1950,1795 1965,1780 2285,1780 2365,1700 3045,1700 3085,1660 3685,1660 3702.88,1677.88 4012.87,1677.88 4020,1685 4225,1685 4415,1875 4585,1875 4630,1920 4660,1920 4685,1945 v1(5250,1945)
  BOTTOM w6.16: J23.15@5135.46,2624.22 5315.78,2624.22 5340,2600 5340,2035 v1(5250,1945)
CAM0_PWR_EN: J6.78 R179.1 | length 3099.9
  TOP w6.16: J6.78@2682.28,654.29 2682.28,727.28 v1(3210,1255) ; v1(4775,1530) 4775,1875 4805,1905 v1(4805,1925)
  ART03 w5.61: v1(3210,1255) 3225,1270 4348.61,1270 4421.81,1343.19 4480.48,1343.19 4493.52,1356.23 4493.52,1408.52 4575,1490 4635,1490 4655,1510 4755,1510 v1(4775,1530)
  BOTTOM w6.16: R179.1@4785,2080.32 4785,1945 v1(4805,1925)
CAM1_NRST: J7.41 J24.22 | length 3094.4
  TOP w6.16: v1(2308.27,2011.61) 2327.95,2031.3 J7.41@2327.95,2110.98
  ART03 w5.61: v1(2308.27,2011.61) 2329.88,1990 2495,1990 2530,1955 2580,1955 2670.88,1864.12 3334.12,1864.12 3373.2,1903.19 3549.43,1903.19 3581.23,1935 4045,1935 4160,2050 5037.99,2050 v1(5090,2102.01)
  BOTTOM w6.16: v1(5090,2102.01) J24.22@5135.46,2102.01
CAM1_PWDN: J7.63 J24.15 | length 3098.6
  TOP w6.16: J7.63@2544.49,2110.98 2544.49,2031.3 v1(2564.17,2011.61)
  ART03 w5.61: v1(2564.17,2011.61) 2580.98,2028.41 2611.59,2028.41 2720.88,1919.12 3004.12,1919.12 3050,1965 3200,1965 3220,1945 3305,1945 3383.2,2023.19 3888.2,2023.19 3995,2130 4400,2130 4440,2090 5040,2090 5075,2125 5130,2125 v1(5195,2060)
  BOTTOM w6.16: J24.15@5135.46,1964.21 5179.21,1964.21 5195,1980 v1(5195,2060)
CAM1_PWR_EN: J5.12 R186.1 | length 4587
  TOP w6.16: v1(1009.05,1819.13) 1048.42,1858.5 J5.12@1048.42,1953.5
  ART03 w5.61: v1(1009.05,1819.13) 1009.05,1535.95 1055,1490 1995,1490 2195.12,1289.88 2749.88,1289.88 2770,1310 3645,1310 3670,1335 v1(4290,1335)
  BOTTOM w6.16: v1(4290,1335) 4290,1570 4315,1595 4615,1595 4650,1630 4650,1708.84 4656.16,1715 R186.1@4700.32,1715
CC1: D29.2 J19.A5 | length 240.9
  TOP w6.16: J19.A5@1125.13,2953.48 1125.13,3015.13 v1(1135,3025)
  BOTTOM w6.16: v1(1135,3025) 1135,2940 1166,2909 D29.2@1166,2872.5
CC2: D29.1 J19.B5 | length 585.4
  TOP w6.16: J19.B5@1007.03,2953.48 v1(1007.03,3022.97)
  BOTTOM w6.16: v1(1007.03,3022.97) 1007.03,3072.03 1020,3085 1140,3085 1155,3070 1155,2950 1202.5,2902.5 1202.5,2834 D29.1@1166,2797.5
CSI_RX_D2N_S0: J23.17 R178.2 | length 191.6
  BOTTOM w4.88: R178.2@4959.68,2695 4971.68,2683 4992,2683 5014.82,2660.18 5098.98,2660.18 5102.38,2663.59 J23.17@5135.46,2663.59
CSI_RX_D2N_S1: J24.12 R180.2 | length 1500.3
  TOP w4.88: v1(4844.39,2688.1) 4837.83,2681.54 4824.54,2681.54 4812.12,2669.11 4812.12,2618.96 4828.44,2602.64 4828.44,2602.45 4870,2560.89 v1(4870,2550)
  BOTTOM w4.88: v1(4844.39,2688.1) 4850.4,2682.09 4867.97,2682.06 R180.2@4880.97,2695 ; v1(4870,2550) 4870,2560.12 4857.62,2572.5 4850.72,2572.5 4802.48,2524.27 ccw(c4805.43,2521.32) 4802.48,2518.37 cw(c4799.54,2515.43) 4802.48,2512.48 4794.57,2504.57 cw(c4791.62,2507.52) 4788.68,2504.57 ccw(c4785.73,2501.62) 4782.79,2504.57 4774.88,2496.66 ccw(c4777.82,2493.71) 4774.88,2490.77 cw(c4771.93,2487.82) 4774.88,2484.88 4766.97,2476.97 cw(c4764.02,2479.91) 4761.07,2476.97 ccw(c4758.13,2474.02) 4755.18,2476.96 4735,2456.78 4735,2432.78 4739.88,2427.9 4792.58,2427.9 4805,2415.48 4805,2395.04 4792.58,2382.62 4739.88,2382.62 4730,2372.74 4730,1950 4778.24,1901.76 5098.98,1901.76 5102.38,1905.16 J24.12@5135.46,1905.16
CSI_RX_D2P_S0: J23.16 R176.2 | length 192.9
  BOTTOM w4.88: R176.2@4959.68,2655 4974.8,2670.12 4986.66,2670.12 5009.48,2647.3 5098.98,2647.3 5102.38,2643.9 J23.16@5135.46,2643.9
CSI_RX_D2P_S1: J24.11 R177.2 | length 1503.5
  TOP w4.88: v1(4844.39,2662.1) 4837.83,2668.66 4829.88,2668.66 4825,2663.78 4825,2624.3 4841.32,2607.97 4841.32,2607.79 4879.11,2570 v1(4890,2570)
  BOTTOM w4.88: v1(4844.39,2662.1) 4846.83,2662.1 4853.33,2668.59 4867.34,2668.59 R177.2@4880.87,2655 ; v1(4890,2570) 4878.34,2570 4862.95,2585.38 4845.38,2585.38 4722.12,2462.12 4722.12,2427.44 4734.54,2415.02 4787.24,2415.02 4792.12,2410.14 4792.12,2400.38 4787.24,2395.5 4734.54,2395.5 4717.12,2378.08 4717.12,1944.66 4772.91,1888.88 5098.98,1888.88 5102.38,1885.47 J24.11@5135.46,1885.47
CSI_RX_D3N_S0: J23.20 R184.2 | length 200.3
  BOTTOM w4.88: R184.2@4959.68,2775 4973.24,2761.44 5013.56,2761.44 5055.76,2719.24 5098.98,2719.24 5102.38,2722.64 J23.20@5135.46,2722.64
CSI_RX_D3N_S1: J24.8 R185.2 | length 1499.9
  TOP w4.88: v1(4765,2550) 4765,2590 4775,2600 4775,2727.78 4808.76,2761.54 4837.93,2761.54 v1(4844.49,2768.1)
  BOTTOM w4.88: v1(4765,2550) 4765,2557.12 4764.66,2557.12 4759.66,2562.12 4742.12,2562.12 4695,2515 4695,2505.12 ccw(c4702.5,2505.12) 4702.5,2497.62 cw(c4702.5,2492.74) 4707.38,2492.74 4707.38,2482.98 cw(c4702.5,2482.98) 4702.5,2478.1 ccw(c4702.5,2470.6) 4695,2470.6 4695,1925 4796.98,1823.02 5098.98,1823.02 5102.38,1826.42 J24.8@5135.46,1826.42 ; v1(4844.49,2768.1) 4851.11,2761.47 4867.44,2761.47 R185.2@4880.97,2775
CSI_RX_D3P_S0: J23.19 R182.2 | length 200.3
  BOTTOM w4.88: R182.2@4959.68,2735 4973.24,2748.56 5008.22,2748.56 5050.43,2706.36 5098.98,2706.36 5102.38,2702.95 J23.19@5135.46,2702.95
CSI_RX_D3P_S1: J24.7 R183.2 | length 1497
  TOP w4.88: v1(4785,2570) 4787.88,2572.88 4787.88,2722.44 4814.09,2748.66 4837.93,2748.66 v1(4844.49,2742.1)
  BOTTOM w4.88: v1(4785,2570) 4770,2570 4765,2575 4736.78,2575 4682.12,2520.34 4682.12,1919.66 4791.65,1810.14 5098.98,1810.14 5102.38,1806.73 J24.7@5135.46,1806.73 ; v1(4844.49,2742.1) 4846.93,2742.1 4853.43,2748.59 4867.44,2748.59 R183.2@4880.97,2735
CTP0_INT: J6.65 J21.11 R162.2 | length 5312.3
  TOP w6.16: v1(2564.17,440) J6.65@2564.17,496.81 ; v1(4655,1450) 4655,1590 4695,1630 4695,1720 4675,1740 4675,2230 4820,2375 v1(5040,2375) 5071.42,2406.42 J21.11@5117.47,2406.42
  ART03 w5.61: v1(2564.17,440) 2795,440 2925,310 3070,310 3090,290 4720,290 4785,355 4965,355 5080.08,470.08 5080.08,1089.92 5000,1170 4870,1170 4660,1380 4660,1445 v1(4655,1450)
  BOTTOM w6.16: R162.2@4989.68,2375 v1(5040,2375)
CTP0_RST: J6.61 J21.12 R166.2 | length 5506.2
  TOP w6.16: v1(2524.8,440) J6.61@2524.8,496.81 ; v1(4615,1450) 4635,1470 4635,1602 4653.92,1620.92 4653.92,2233.92 4815,2395 5011.2,2395 v1(5042.3,2426.11) J21.12@5117.47,2426.11
  ART03 w5.61: v1(2524.8,440) 2544.8,420 2785,420 2918.5,286.5 3058.5,286.5 3075,270 4725,270 4790,335 4970,335 5100,465 5100,1100 4975,1225 4840,1225 4675,1390 4675,1460 4665,1470 4635,1470 v1(4615,1450)
  BOTTOM w6.16: R166.2@4989.68,2415 5031.2,2415 v1(5042.3,2426.11)
CTP1_INT: J7.55 J22.11 R164.2 | length 4399.4
  TOP w6.16: v1(2465.75,2051.61) J7.55@2465.75,2110.98 ; R164.2@4989.68,1560 5012.05,1560 v1(5035.63,1536.42) J22.11@5117.47,1536.42
  BOTTOM w6.16: v1(2465.75,2051.61) 2484.83,2032.53 2484.83,1979.83 2418.21,1913.21 2300.36,1913.21 2270,1882.85 2270,1645 2425.62,1489.38 2545.62,1489.38 3065,970 3677,970 3737,1030 4308.07,1030 4325,1046.93 4325,1470 4425,1570 4640,1570 4665,1595 5042.77,1595 5054.08,1583.69 5054.08,1554.87 v1(5035.63,1536.42)
CTP1_RST: J7.57 J22.12 R168.2 | length 4367.5
  TOP w6.16: v1(2465.75,2011.61) 2485.43,2031.3 J7.57@2485.43,2110.98 ; R168.2@4989.68,1600 5010.79,1600 v1(5035,1575.79) 5054.68,1556.11 J22.12@5117.47,1556.11
  BOTTOM w6.16: v1(2465.75,2011.61) 2465.75,1985.75 2410,1930 2285,1930 2250,1895 2250,1635 2413.3,1471.7 2533.3,1471.7 3055,950 3687,950 3747,1010 4316.36,1010 4345,1038.64 4345,1460 4435,1550 4650,1550 4675.79,1575.79 v1(5035,1575.79)
DBG_RX: R40.2 U10.2 | length 108.8
  BOTTOM w6.16: R40.2@330,724.68 349.68,705 388.32,705 405,688.32 U10.2@405,669.57
DBG_RXD: D6.2 J9.3 R40.1 | length 217.8
  BOTTOM w6.16: J9.3@120,666.54 138.78,685.32 D6.2@290,685.32 R40.1@330,685.32
DBG_TX: R39.2 U9.4 | length 55.9
  BOTTOM w6.16: R39.2@330,564.68 345.75,580.43 U9.4@379.41,580.43
DBG_TXD: D5.2 J9.2 R39.1 | length 227.1
  BOTTOM w6.16: J9.2@120,566.54 248.78,566.54 D5.2@290,525.32 R39.1@330,525.32
DM4: D38.2 J27.36 R210.1 | length 372.5
  TOP w6.23: J27.36@3889.82,2168.04 3889.82,2122.38 3881.18,2113.75 3881.18,2031.23 3887.42,2025 3900,2025 3910,2015 D38.2@3910,1994.68 3891.37,1994.68 3885.14,1988.45 3885.14,1935.14 3864.23,1914.23 3864.23,1880.46 3869.3,1875.39 3880.71,1875.39 R210.1@3890.32,1885
DP4: D39.2 J27.38 R211.1 | length 408.4
  TOP w6.23: J27.38@3858.32,2168.04 3858.32,2122.38 3866.95,2113.75 3866.95,2096.58 cw(c3860.98,2096.58) 3860.98,2090.61 ccw(c3860.98,2084.63) 3855,2084.63 3855,2071.66 ccw(c3860.98,2071.66) 3860.98,2065.69 cw(c3860.98,2059.71) 3866.95,2059.71 3866.95,2031.95 3860,2025 3851.23,2025 3845,2018.77 D39.2@3845,1994.68 3864.68,1994.68 3870.91,1988.45 3870.91,1941.04 3850,1920.12 3850,1874.57 3864.57,1860 3875.32,1860 R211.1@3890.32,1845
DSI0_RST: J5.60 J21.15 | length 4231.2
  TOP w6.16: v1(1520.86,1895) J5.60@1520.86,1953.5 ; v1(4545,1915) 4560,1930 4560,2080 4595,2115 4595,2260 4820.16,2485.16 J21.15@5117.47,2485.16
  ART03 w5.61: v1(1520.86,1895) 1579.05,1836.81 2288.2,1836.81 2330,1795 2430,1795 2491.8,1733.19 3061.8,1733.19 3091.75,1703.25 3646.23,1703.25 3681.64,1738.66 4213.66,1738.66 4390,1915 v1(4545,1915)
DSI0_TE: J5.58 R160.1 | length 4014.2
  TOP w6.16: J5.58@1501.17,1953.5 1501.17,1874.68 v1(1520.86,1855) ; v1(4590,1915) 4590,2070 4615,2095 4615,2250 4815,2450 R160.1@4850.32,2450
  ART03 w5.61: v1(1520.86,1855) 1560.86,1815 1960,1815 1975,1800 2295,1800 2320,1775 2415,1775 2474.25,1715.75 3054.25,1715.75 3084.25,1685.75 3665.75,1685.75 3691.8,1711.81 3843.2,1711.81 3855,1700 4000,1700 4022.27,1722.27 4232.27,1722.27 4405,1895 4570,1895 v1(4590,1915)
DSI1_RST: J7.53 J22.15 | length 4544.8
  TOP w6.16: v1(2426.38,2011.61) 2446.06,2031.3 J7.53@2446.06,2110.98 ; v1(4775,1490) 4794.08,1509.08 4794.08,1639.08 4820,1665 5008.02,1665 5057.86,1615.16 J22.15@5117.47,1615.16
  BOTTOM w6.16: v1(2426.38,2011.61) 2426.38,1996.38 2390,1960 2255,1960 2210,1915 2210,1618.14 2398.14,1430 2500,1430 3020,910 3712,910 3767,965 4335,965 4385,1015 4385,1440 4435,1490 4650,1490 4669.08,1509.08 4755.92,1509.08 v1(4775,1490)
DSI1_TE: J7.51 R161.1 | length 4275.9
  TOP w6.16: v1(2426.38,2051.61) J7.51@2426.38,2110.98 ; v1(4815,1530) 4815,1620 4835,1640 R161.1@4950.32,1640
  BOTTOM w6.16: v1(2426.38,2051.61) 2445.46,2032.53 2445.46,1990.46 2400,1945 2270,1945 2230,1905 2230,1625 2405,1450 2520,1450 3040,930 3702,930 3762,990 4324.64,990 4365,1030.36 4365,1450 4425,1510 4640,1510 4679.08,1549.08 4795.92,1549.08 v1(4815,1530)
EDP_AUXN: C146.2 J25.10 R191.2 | length 299.6
  TOP w4.88: C146.2@4869.68,665 4869.68,646.32 4874.56,641.44 4989.8,641.44 4994.68,646.32 R191.2@4994.68,665 5010,665 5031.67,643.33 5080.99,643.33 5084.39,646.74 J25.10@5117.47,646.74
EDP_AUXP: C147.2 J25.9 R188.2 | length 301.1
  TOP w4.88: C147.2@4869.68,605 4869.68,623.68 4874.56,628.56 4989.8,628.56 4994.68,623.68 R188.2@4994.68,605 5010,605 5035.45,630.45 5080.99,630.45 5084.39,627.05 J25.9@5117.47,627.05
EDP_BL_EN: J4.39 J25.22 | length 4656.1
  TOP w6.16: v1(1324.01,435) J4.39@1324.01,496.81 ; J25.22@5117.47,882.96 5152.96,882.96 v1(5160,890)
  ART03 w5.61: v1(1324.01,435) 1364.01,395 1980,395 2015,360 2695,360 2865,190 4750,190 4820,260 5015,260 5204.99,450 5204.99,815 5185,835 5185,865 v1(5160,890)
EDP_BL_PWM: J5.5 J25.23 | length 5312
  TOP w6.16: J5.5@989.36,2110.98 989.36,2175.63 v1(1028.73,2215) ; v1(5034.94,915) 5047.3,902.64 J25.23@5117.47,902.64
  ART03 w5.61: v1(1028.73,2215) 1009.93,2196.2 1009.93,1854.93 990,1834.99 990,1525.01 1075,1440 2015,1440 2220,1235 4365,1235 4380,1250 4430,1250 4502,1178 4757,1178 4840,1095 5005,1095 5034.94,1065.06 v1(5034.94,915)
EDP_HPDIN_M0: J6.66 J25.17 | length 3905.6
  TOP w6.16: J6.66@2564.17,654.29 2564.17,794.17 v1(2695,925) ; J25.17@5117.47,784.53 v1(5185,784.53)
  ART03 w5.61: v1(2890,224.08) 2904.08,210 4745,210 4815,280 5005,280
  ART03 w6.16: 5005,280 5185,460 v1(5185,784.53)
  BOTTOM w6.16: v1(2695,925) 2800,820 2800,804.99 2803.08,801.9 2803.08,786.1 2800,783.01 2800,490 2890,400 v1(2890,224.08)
EDP_PWR_EN: J6.76 R192.1 R196.1 | length 2734
  TOP w6.16: J6.76@2662.6,654.29 2662.6,747.6 v1(3085,1170) ; v1(4410,1170) 4430,1150 4633,1150 4658,1125 4658,784.84 4668.16,774.68 R196.1@4720,774.68
  ART03 w5.61: v1(3085,1170) v1(4410,1170)
  BOTTOM w6.16: R192.1@4410,1124.68 v1(4410,1170)
EDP_TP_INT: J7.65 J26.2 R189.2 | length 4488.9
  TOP w6.16: J26.2@2440.94,104.49 2480.43,65 2693.27,65 2715,86.73 2715,140 2750,175 3480,175 3500,195 v1(3500,995) ; v1(2564.17,2051.61) J7.65@2564.17,2110.98
  BOTTOM w6.16: R189.2@2434.68,485 2434.68,455.32 2495,395 2495,158.55 J26.2@2440.94,104.49 ; v1(2564.17,2051.61) 2530,2017.44 2530,1995 2450,1915 2439.95,1915 2419.95,1895 2341.57,1895 2295,1848.43 2295,1650 2440,1505 2560,1505 3070,995 v1(3500,995)
EDP_TP_RESET: J6.57 J26.3 R190.2 | length 598.8
  TOP w6.16: J6.57@2485.43,496.81 v1(2485.43,555)
  BOTTOM w6.16: R190.2@2434.68,525 2455.43,525 v1(2485.43,555) 2505,535.43 2505,420 2535,390 2535,119.81 J26.3@2519.68,104.49
EDP_TX_AUXN: C146.1 J6.62 | length 3191.5
  TOP w4.88: J6.62@2524.8,654.29 2524.8,701.15 2522,703.95 2522,837 2555.4,870.4 2555.4,912.44 v1(2562.96,920) ; v1(4724.49,559.16) 4730,564.66 4730,620 4751.44,641.44 4825.44,641.44 4830.32,646.32 C146.1@4830.32,665
  ART03 w4.44: v1(2562.96,920) 2550,932.96 2550,947.41 2565.15,962.56 2583.14,962.56 cw(c2583.14,958.78) 2586.92,958.78 ccw(c2590.7,958.78) 2590.7,955 2600.9,955 ccw(c2600.9,958.78) 2604.68,958.78 cw(c2608.46,958.78) 2608.46,962.56 2618.66,962.56 cw(c2618.66,958.78) 2622.44,958.78 ccw(c2626.22,958.78) 2626.22,955 2636.42,955 ccw(c2636.42,958.78) 2640.2,958.78 cw(c2643.98,958.78) 2643.98,962.56 3785.15,962.56 3855.15,1032.56 4574.85,1032.56 4634.49,972.92 4634.49,767.92 4676.24,726.17 4676.24,719.89 4658.97,702.62 4658.97,686.03 4672.54,672.46 4689.12,672.46 4706.39,689.74 4712.67,689.74 4732.56,669.85 4732.56,566.99 4724.73,559.16 v1(4724.49,559.16)
EDP_TX_AUXP: C147.1 J6.60 | length 3188.3
  TOP w4.88: J6.60@2505.12,654.29 2505.12,700.12 2509.12,704.12 2509.12,842.34 2542.52,875.74 2542.52,914.44 v1(2536.96,920) ; v1(4750.49,559.16) 4742.88,566.77 4742.88,614.66 4756.78,628.56 4825.44,628.56 4830.32,623.68 C147.1@4830.32,605
  ART03 w4.44: v1(2536.96,920) 2537.56,920.6 2537.56,952.56 2560,975 3780,975 3850,1045 4580,1045 4646.93,978.07 4646.93,773.07 4688.68,731.32 4688.68,714.74 4671.4,697.47 4671.4,691.19 4677.69,684.9 4683.97,684.9 4701.24,702.17 4717.82,702.17 4745,675 4745,564.65 v1(4750.49,559.16)
EDP_TX_D0N: J6.44 J25.6 | length 3497.6
  TOP w4.88: J6.44@2347.64,654.29 2347.64,701.15 2344.24,704.55 2344.24,913.44 v1(2350.8,920) ; v1(5059.39,564.84) 5066.67,572.12 5113.35,572.12 J25.6@5117.47,568
  ART03 w4.44: v1(2350.8,920) 2344.01,926.78 2344.01,949.01 2462.56,1067.56 3775.15,1067.56 3832.59,1125 4580,1125 4702.56,1002.44 4702.56,809.85 4883.63,628.78 4963.63,628.78 5015.79,576.62 5047.61,576.62 v1(5059.39,564.84)
EDP_TX_D0P: J6.42 J25.7 | length 3512.9
  TOP w4.88: v1(2324.8,920) 2331.36,913.44 2331.36,704.55 2327.95,701.15 J6.42@2327.95,654.29 ; v1(5059.39,590.84) 5065.23,585 5114.79,585 J25.7@5117.47,587.68
  ART03 w4.44: v1(2324.8,920) 2331.57,926.78 2331.57,954.17 2457.41,1080 3770,1080 3827.44,1137.44 4585.15,1137.44 4715,1007.59 4715,815 4888.78,641.22 4968.78,641.22 5020.94,589.06 5057.61,589.06 v1(5059.39,590.84)
EDP_TX_D1N: J6.48 J25.3 | length 3547.8
  TOP w4.88: J6.48@2387.01,654.29 2387.01,701.15 2383.61,704.55 2383.61,798.6 2447.61,862.6 2447.61,912.44 v1(2455.16,920) ; v1(4984.39,505.78) 4991.67,513.06 5113.35,513.06 J25.3@5117.47,508.94
  ART03 w4.44: v1(2455.16,920) 2445,930.16 2445,975 2492.56,1022.56 3790.15,1022.56 3835.15,1067.56 4587.44,1067.56 4666.93,988.07 4666.93,790.48 4811.15,646.25 4811.15,639.97 4794.54,623.36 4794.54,606.77 4808.11,593.2 4824.69,593.2 4841.31,609.82 4847.59,609.82 4853.87,603.54 4853.87,597.26 4834.75,578.14 4834.75,561.56 4848.32,547.99 4864.91,547.99 4884.02,567.11 4890.3,567.11 4941.85,515.56 4974.61,515.56 v1(4984.39,505.78)
EDP_TX_D1P: J6.46 J25.4 | length 3561.1
  TOP w4.88: J6.46@2367.32,654.29 2367.32,701.15 2370.72,704.55 2370.72,803.94 2434.72,867.94 2434.72,914.44 v1(2429.16,920) ; v1(4984.39,531.78) 4990.23,525.94 5114.78,525.94 J25.4@5117.47,528.63
  ART03 w4.44: v1(2429.16,920) 2432.56,923.39 2432.56,980.15 2487.41,1035 3785,1035 3830,1080 4592.59,1080 4679.37,993.22 4679.37,795.63 4823.59,651.41 4823.59,634.82 4806.98,618.21 4806.98,611.93 4813.26,605.64 4819.54,605.64 4836.15,622.26 4852.74,622.26 4866.31,608.69 4866.31,592.11 4847.19,572.99 4847.19,566.71 4853.47,560.43 4859.75,560.43 4878.87,579.54 4895.45,579.54 4947,528 4980.61,528 v1(4984.39,531.78)
EXT_PWR_EN: J4.27 R1.1 R3.1 R19.1 R24.1 | length 3219.1
  TOP w6.16: R19.1@464.68,1205 540,1205 v1(570,1175) ; J4.27@1205.9,496.81 v1(1205.9,555)
  ART03 w5.61: v1(370,2350) 395,2325 395,1810 615,1590 v1(615,1485) 615,1400 590,1375 590,1195 v1(570,1175) 550,1155 550,1065 572,1043 619,1043 791,871 1103,871 1205.9,768.1 v1(1205.9,555)
  BOTTOM w6.16: R24.1@180,2365.32 204.88,2340.44 360.44,2340.44 v1(370,2350) ; R3.1@620,1630.32 620,1595 615,1590 v1(615,1485) 825,1485 839.68,1470.32 R1.1@839.68,1415
FAN: C30.1 Q1.2 R9.2 R10.2 R12.1
FSPI_CLK: J6.29 U8.6 | length 1415.9
  TOP w6.16: J6.29@2209.84,496.81 2209.84,575.62 v1(2229.53,595.31) ; v1(3155,775) 3245,685 U8.6@3245,602.52
  ART03 w5.61: v1(2229.53,595.31) 2229.53,639.52 2280,690 2341.76,690 2347.37,695.61 2347.37,709.39 2352.98,715 2364.2,715 2369.81,709.39 2369.81,695.61 2375.42,690 2386.64,690 2392.25,695.61 2392.25,709.39 2397.86,715 2409.08,715 2414.69,709.39 2414.69,695.61 2420.3,690 2702.94,690 2787.94,775 v1(3155,775)
FSPI_CS0N: J6.31 U8.1 | length 1423.6
  TOP w6.16: J6.31@2229.53,496.81 v1(2229.53,555.31) ; v1(3295,775) 3345,825 U8.1@3345,917.48
  ART03 w5.61: v1(2229.53,555.31) 2249.21,575 2249.21,624.21 2295,670 2715,670 2800,755 3190,755 3230,795 3275,795 v1(3295,775)
FSPI_D0: J6.33 J8.2 U8.5 | length 1775.3
  TOP w6.16: J6.33@2249.21,496.81 2249.21,575.62 v1(2268.9,595.31) ; v1(3155,735) 3195,695 U8.5@3195,602.52
  ART03 w5.61: v1(2268.9,595.31) 2268.9,618.9 2295,645 2722.73,645 2812.73,735 3032.84,735 3038.45,729.39 3038.45,705.61 3044.06,700 3055.28,700 3060.89,705.61 3060.89,729.39 3066.5,735 3077.72,735 3083.33,729.39 3083.33,705.61 3088.94,700 3100.16,700 3105.77,705.61 3105.77,729.39 3111.38,735 3125,735 3130,730 3130,705 3135,700 3150,700 3155,705 v1(3155,735)
  BOTTOM w6.16: v1(3155,735) 3220,670 J8.2@3220,375
FSPI_D1: J6.35 U8.2 | length 1420.2
  TOP w6.16: J6.35@2268.9,496.81 v1(2268.9,555.31) ; v1(3245,775) 3295,825 U8.2@3295,917.48
  ART03 w5.61: v1(2268.9,555.31) 2289.46,575.88 2289.46,614.46 2300,625 2730.57,625 2820.57,715 3000,715 3035,680 3204.39,680 3210,685.61 3210,705 3205,710 3185,710 3180,715 3180,729.39 3185.61,735 3205,735 v1(3245,775)
FSPI_D2: J6.37 R36.2 U8.3 | length 1819.3
  TOP w6.16: J6.37@2288.58,496.81 2288.58,575.62 v1(2308.27,595.31) ; v1(3245,735) 3220,760 3220,825 3245,850 U8.3@3245,917.48 3245,965 3260,980 3425,980 3445,960 R36.2@3445,824.68
  ART03 w5.61: v1(2308.27,595.31) 2317.96,605 2738.41,605 2828.41,695 2990,695 3025,660 3220,660 3230,670 3230,704.39 3235.61,710 3270,710 3275,715 3275,729.39 3269.39,735 v1(3245,735)
FSPI_D3: J6.39 R37.2 U8.7 | length 1558.6
  TOP w6.16: J6.39@2308.27,496.81 v1(2308.27,555.31) ; U8.7@3295,602.52 v1(3295,735) 3384.68,824.68 R37.2@3405,824.68
  ART03 w5.61: v1(2308.27,555.31) 2337.96,585 2745,585 2835,675 2980,675 3015,640 3289.39,640 3295,645.61 3295,660 3290,665 3255,665 3250,670 3250,684.39 3255.61,690 3290,690 3295,695 v1(3295,735)
GMAC1_INT: J5.10 R111.1 | length 4200.8
  TOP w6.16: v1(949.99,1819.13) 974.13,1819.13 1028.73,1873.73 J5.10@1028.73,1953.5 ; R111.1@3565,1925.32 3565,1885 3575,1875 3620,1875 3635,1890 3685,1890 3700,1875 3780,1875 3790,1865 3790,1790 v1(3765,1765)
  ART03 w5.61: v1(949.99,1819.13) 990,1859.14 990,2275 1050,2335 1305,2335 1345,2295 1345,2135 1565,1915 1585,1915 1600,1900 1600,1885 1609.37,1875.63 2394.37,1875.63 2478.2,1791.81 2503.2,1791.81 2545,1750 3600,1750 3615,1765 v1(3765,1765)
